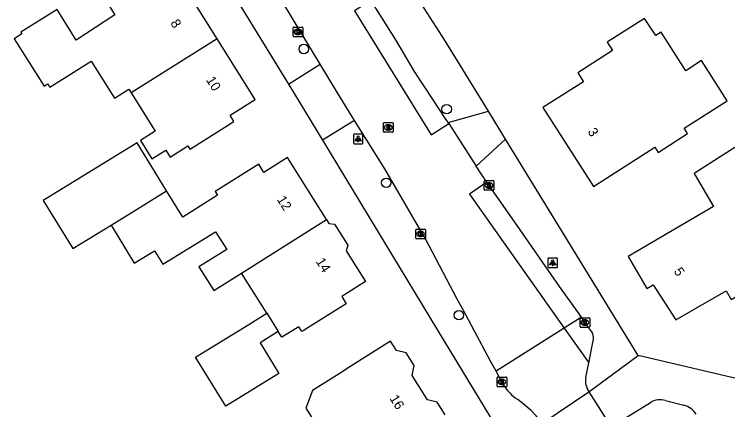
# Model space of a CAD drawing. Extents: x 161354 to 161876, y 382161 to 382804.
# Drawn here: x 161455.3 to 161529.3, y 382580.4 to 382621.3 of the extents above; entities that cross this region are included whole.
import ezdxf

# ---------------------------------------------------------------- set-up
doc = ezdxf.new("R2010")
doc.units = 0
for name, color, linetype in [('IMGEO_Boom', 7, 'Continuous'), ('IMGEO_Kolk', 7, 'Continuous'), ('IMGEO_Lichtpunt', 7, 'Continuous'), ('IMGEO_Pand', 7, 'Continuous'), ('IMGEO_Pand_nummerreeks', 7, 'Continuous'), ('IMGEO_Parkeervlak_gesloten', 7, 'Continuous'), ('IMGEO_Rijbaan_lokaal_gesloten', 7, 'Continuous'), ('IMGEO_Rijbaan_lokaal_open', 7, 'Continuous'), ('IMGEO_Rioolput', 7, 'Continuous'), ('IMGEO_Voetpad_open', 7, 'Continuous')]:
    doc.layers.add(name, color=color, linetype=linetype)

msp = doc.modelspace()

# ---------------------------------------------------------------- linework, layer by layer
at = {"layer": 'IMGEO_Boom'}
for centre in [(161485.332, 382617.715), (161500.14, 382611.487), (161493.875, 382603.871), (161501.41, 382590.158)]:
    msp.add_circle(centre, 0.489, dxfattribs=at)
at = {"layer": 'IMGEO_Kolk'}
for p, q in [((161484.232, 382619.064), (161484.232, 382619.916)), ((161484.307, 382619.99), (161485.159, 382619.99)), ((161485.233, 382619.916), (161485.233, 382619.064)), ((161484.743, 382619.21), (161484.718, 382619.21)), ((161484.72, 382619.77), (161484.745, 382619.77)), ((161485.159, 382618.99), (161484.307, 382618.99)), ((161504.036, 382603.163), (161504.036, 382604.015)), ((161504.111, 382604.089), (161504.963, 382604.089)), ((161504.524, 382603.869), (161504.549, 382603.869)), ((161505.037, 382604.015), (161505.037, 382603.163)), ((161504.963, 382603.089), (161504.111, 382603.089)), ((161504.547, 382603.309), (161504.522, 382603.309)), ((161496.933, 382598.142), (161496.933, 382598.994)), ((161497.008, 382599.068), (161497.86, 382599.068)), ((161497.421, 382598.848), (161497.446, 382598.848)), ((161497.934, 382598.994), (161497.934, 382598.142)), ((161497.86, 382598.068), (161497.008, 382598.068)), ((161497.444, 382598.288), (161497.419, 382598.288)), ((161513.962, 382588.975), (161513.962, 382589.827)), ((161514.037, 382589.901), (161514.889, 382589.901)), ((161514.45, 382589.681), (161514.475, 382589.681)), ((161514.963, 382589.827), (161514.963, 382588.975)), ((161514.889, 382588.901), (161514.037, 382588.901)), ((161514.473, 382589.121), (161514.448, 382589.121)), ((161505.436, 382583.748), (161506.288, 382583.748)), ((161505.361, 382582.822), (161505.361, 382583.674)), ((161505.872, 382582.968), (161505.847, 382582.968)), ((161505.849, 382583.528), (161505.874, 382583.528)), ((161506.362, 382583.674), (161506.362, 382582.822)), ((161506.288, 382582.748), (161505.436, 382582.748))]:
    msp.add_line(p, q, dxfattribs=at)
for points in [[(161484.232, 382619.064), (161484.232, 382619.916)], [(161484.307, 382619.99), (161485.159, 382619.99)], [(161485.233, 382619.916), (161485.233, 382619.064)], [(161484.553, 382619.69), (161484.676, 382619.69), (161484.676, 382619.539), (161484.806, 382619.69), (161484.97, 382619.69), (161484.824, 382619.539), (161484.977, 382619.29), (161484.825, 382619.29), (161484.74, 382619.454), (161484.676, 382619.387), (161484.676, 382619.29), (161484.553, 382619.29), (161484.553, 382619.69)], [(161485.159, 382618.99), (161484.307, 382618.99)], [(161504.036, 382603.163), (161504.036, 382604.015)], [(161504.111, 382604.089), (161504.963, 382604.089)], [(161504.357, 382603.789), (161504.48, 382603.789), (161504.48, 382603.638), (161504.61, 382603.789), (161504.774, 382603.789), (161504.628, 382603.638), (161504.781, 382603.389), (161504.629, 382603.389), (161504.544, 382603.553), (161504.48, 382603.486), (161504.48, 382603.389), (161504.357, 382603.389), (161504.357, 382603.789)], [(161505.037, 382604.015), (161505.037, 382603.163)], [(161504.963, 382603.089), (161504.111, 382603.089)], [(161496.933, 382598.142), (161496.933, 382598.994)], [(161497.008, 382599.068), (161497.86, 382599.068)], [(161497.254, 382598.768), (161497.377, 382598.768), (161497.377, 382598.617), (161497.507, 382598.768), (161497.671, 382598.768), (161497.525, 382598.617), (161497.678, 382598.368), (161497.526, 382598.368), (161497.441, 382598.532), (161497.377, 382598.465), (161497.377, 382598.368), (161497.254, 382598.368), (161497.254, 382598.768)], [(161497.934, 382598.994), (161497.934, 382598.142)], [(161497.86, 382598.068), (161497.008, 382598.068)], [(161513.962, 382588.975), (161513.962, 382589.827)], [(161514.037, 382589.901), (161514.889, 382589.901)], [(161514.283, 382589.601), (161514.406, 382589.601), (161514.406, 382589.45), (161514.536, 382589.601), (161514.7, 382589.601), (161514.554, 382589.45), (161514.707, 382589.201), (161514.555, 382589.201), (161514.47, 382589.365), (161514.406, 382589.298), (161514.406, 382589.201), (161514.283, 382589.201), (161514.283, 382589.601)], [(161514.963, 382589.827), (161514.963, 382588.975)], [(161514.889, 382588.901), (161514.037, 382588.901)], [(161505.436, 382583.748), (161506.288, 382583.748)], [(161505.361, 382582.822), (161505.361, 382583.674)], [(161505.682, 382583.448), (161505.805, 382583.448), (161505.805, 382583.297), (161505.935, 382583.448), (161506.099, 382583.448), (161505.953, 382583.297), (161506.106, 382583.048), (161505.954, 382583.048), (161505.869, 382583.212), (161505.805, 382583.145), (161505.805, 382583.048), (161505.682, 382583.048), (161505.682, 382583.448)], [(161506.362, 382583.674), (161506.362, 382582.822)], [(161506.288, 382582.748), (161505.436, 382582.748)]]:
    msp.add_lwpolyline(points, dxfattribs=at)
for centre, start, end in [((161484.309, 382619.914), 91.55205, 178.44795), ((161484.309, 382619.914), 91.55205, 178.44795), ((161485.157, 382619.914), 1.55205, 88.44795), ((161485.157, 382619.914), 1.55205, 88.44795), ((161484.309, 382619.066), 181.55205, 268.44795), ((161484.309, 382619.066), 181.55205, 268.44795), ((161485.157, 382619.066), 271.55205, 358.44795), ((161485.157, 382619.066), 271.55205, 358.44795), ((161504.113, 382604.013), 91.55205, 178.44795), ((161504.113, 382604.013), 91.55205, 178.44795), ((161504.961, 382604.013), 1.55205, 88.44795), ((161504.961, 382604.013), 1.55205, 88.44795), ((161504.113, 382603.165), 181.55205, 268.44795), ((161504.113, 382603.165), 181.55205, 268.44795), ((161504.961, 382603.165), 271.55205, 358.44795), ((161504.961, 382603.165), 271.55205, 358.44795), ((161497.01, 382598.992), 91.55205, 178.44795), ((161497.01, 382598.992), 91.55205, 178.44795), ((161497.858, 382598.992), 1.55205, 88.44795), ((161497.858, 382598.992), 1.55205, 88.44795), ((161497.01, 382598.144), 181.55205, 268.44795), ((161497.01, 382598.144), 181.55205, 268.44795), ((161497.858, 382598.144), 271.55205, 358.44795), ((161497.858, 382598.144), 271.55205, 358.44795), ((161514.039, 382589.825), 91.55205, 178.44795), ((161514.039, 382589.825), 91.55205, 178.44795), ((161514.887, 382589.825), 1.55205, 88.44795), ((161514.887, 382589.825), 1.55205, 88.44795), ((161514.039, 382588.977), 181.55205, 268.44795), ((161514.039, 382588.977), 181.55205, 268.44795), ((161514.887, 382588.977), 271.55205, 358.44795), ((161514.887, 382588.977), 271.55205, 358.44795), ((161505.438, 382583.672), 91.55205, 178.44795), ((161505.438, 382583.672), 91.55205, 178.44795), ((161506.286, 382583.672), 1.55205, 88.44795), ((161506.286, 382583.672), 1.55205, 88.44795), ((161505.438, 382582.824), 181.55205, 268.44795), ((161505.438, 382582.824), 181.55205, 268.44795), ((161506.286, 382582.824), 271.55205, 358.44795), ((161506.286, 382582.824), 271.55205, 358.44795)]:
    msp.add_arc(centre, 0.0765, start, end, dxfattribs=at)
for centre, major_axis, ratio, start_param, end_param in [((161484.719, 382619.49), (-0.387, 0.002), 0.722429, 4.712389, 7.853982), ((161484.744, 382619.49), (-0.39, 0.002), 0.717154, 1.570796, 4.712389), ((161504.523, 382603.589), (-0.387, 0.002), 0.722429, 4.712389, 7.853982), ((161504.548, 382603.589), (-0.39, 0.002), 0.717154, 1.570796, 4.712389), ((161497.42, 382598.568), (-0.387, 0.002), 0.722429, 4.712389, 7.853982), ((161497.445, 382598.568), (-0.39, 0.002), 0.717154, 1.570796, 4.712389), ((161514.449, 382589.401), (-0.387, 0.002), 0.722429, 4.712389, 7.853982), ((161514.474, 382589.401), (-0.39, 0.002), 0.717154, 1.570796, 4.712389), ((161505.848, 382583.248), (-0.387, 0.002), 0.722429, 4.712389, 7.853982), ((161505.873, 382583.248), (-0.39, 0.002), 0.717154, 1.570796, 4.712389)]:
    msp.add_ellipse(centre, major_axis=major_axis, ratio=ratio, start_param=start_param, end_param=end_param, dxfattribs=at)
at = {"layer": 'IMGEO_Lichtpunt'}
for p, q in [((161490.471, 382608.814), (161490.471, 382608.007)), ((161490.471, 382608.814), (161490.471, 382608.007)), ((161491.373, 382608.909), (161490.565, 382608.909)), ((161491.373, 382608.909), (161490.565, 382608.909)), ((161491.467, 382608.007), (161491.467, 382608.814)), ((161491.467, 382608.007), (161491.467, 382608.814)), ((161490.565, 382607.913), (161491.373, 382607.913)), ((161490.565, 382607.913), (161491.373, 382607.913)), ((161510.624, 382595.981), (161510.624, 382595.174)), ((161510.624, 382595.981), (161510.624, 382595.174)), ((161511.526, 382596.076), (161510.718, 382596.076)), ((161511.526, 382596.076), (161510.718, 382596.076)), ((161511.62, 382595.174), (161511.62, 382595.981)), ((161511.62, 382595.174), (161511.62, 382595.981)), ((161510.718, 382595.08), (161511.526, 382595.08)), ((161510.718, 382595.08), (161511.526, 382595.08))]:
    msp.add_line(p, q, dxfattribs=at)
for points in [[(161490.845, 382608.478), (161490.884, 382608.45), (161490.696, 382608.188), (161490.658, 382608.215), (161490.845, 382608.478)], [(161490.947, 382608.43), (161490.994, 382608.43), (161490.994, 382608.108), (161490.947, 382608.108), (161490.947, 382608.43)], [(161491.057, 382608.45), (161491.095, 382608.477), (161491.282, 382608.215), (161491.243, 382608.187), (161491.057, 382608.45)], [(161510.998, 382595.645), (161511.037, 382595.617), (161510.849, 382595.355), (161510.811, 382595.382), (161510.998, 382595.645)], [(161511.1, 382595.597), (161511.147, 382595.597), (161511.147, 382595.275), (161511.1, 382595.275), (161511.1, 382595.597)], [(161511.21, 382595.617), (161511.248, 382595.644), (161511.435, 382595.382), (161511.396, 382595.354), (161511.21, 382595.617)]]:
    msp.add_lwpolyline(points, dxfattribs=at)
for centre in [(161490.97, 382608.612), (161511.123, 382595.779)]:
    msp.add_circle(centre, 0.0994, dxfattribs=at)
for centre, start, end in [((161490.565, 382608.814), 90, 180), ((161490.565, 382608.814), 90, 180), ((161491.373, 382608.814), 0, 90), ((161491.373, 382608.814), 0, 90), ((161490.565, 382608.007), 180, 270), ((161490.565, 382608.007), 180, 270), ((161491.373, 382608.007), 270, 0), ((161491.373, 382608.007), 270, 360), ((161510.718, 382595.981), 90, 180), ((161510.718, 382595.981), 90, 180), ((161511.526, 382595.981), 0, 90), ((161511.526, 382595.981), 0, 90), ((161510.718, 382595.174), 180, 270), ((161510.718, 382595.174), 180, 270), ((161511.526, 382595.174), 270, 0), ((161511.526, 382595.174), 270, 360)]:
    msp.add_arc(centre, 0.0946, start, end, dxfattribs=at)
at = {"layer": 'IMGEO_Pand'}
for points in [[(161476.368, 382618.775), (161472.42, 382625.057), (161469.853, 382623.444), (161469.094, 382624.652), (161465.175, 382622.189), (161465.761, 382621.258), (161461.76, 382618.626), (161459.765, 382621.802), (161456.015, 382619.445), (161456.122, 382619.276), (161455.335, 382618.782), (161458.416, 382613.881), (161458.792, 382614.118), (161459.015, 382613.762), (161463.307, 382616.459), (161465.723, 382612.615), (161467.215, 382613.553), (161467.454, 382613.173)], [(161520.354, 382606.692), (161521.716, 382607.564), (161522.071, 382607.009), (161525.112, 382608.956), (161524.756, 382609.51), (161529.198, 382612.354), (161526.536, 382616.513), (161524.908, 382615.471), (161522.358, 382619.455), (161521.829, 382619.116), (161520.641, 382620.888), (161516.784, 382618.417), (161517.328, 382617.566), (161513.723, 382615.258), (161514.315, 382614.332), (161510.12, 382611.646), (161515.345, 382603.485), (161520.354, 382606.692)], [(161467.454, 382613.173), (161469.94, 382609.218), (161468.409, 382608.256), (161469.604, 382606.355), (161471.042, 382607.259), (161471.497, 382606.535), (161473.322, 382607.682), (161473.527, 382607.355), (161473.862, 382607.566), (161478.095, 382610.226), (161477.7, 382610.854), (161480.313, 382612.497), (161476.368, 382618.775)], [(161476.368, 382618.775), (161467.454, 382613.173)], [(161523.9, 382589.662), (161529.1, 382592.687), (161529.627, 382591.781), (161533.997, 382594.323), (161533.666, 382594.894), (161535.542, 382595.986), (161532.083, 382601.934), (161535.61, 382603.986), (161532.589, 382609.182), (161525.776, 382604.825), (161527.773, 382601.394), (161518.94, 382596.251), (161520.875, 382592.926), (161521.528, 382593.306), (161523.9, 382589.662)], [(161471.125, 382603.016), (161468.076, 382607.993), (161458.345, 382602.032), (161461.393, 382597.056), (161465.363, 382599.487)], [(161487.695, 382600.06), (161483.661, 382606.478), (161481.2, 382604.932), (161480.66, 382605.791), (161476.162, 382602.965), (161476.407, 382602.575), (161472.788, 382600.3), (161471.125, 382603.016)], [(161465.363, 382599.487), (161467.456, 382600.769), (161471.125, 382603.016)], [(161478.886, 382594.523), (161487.695, 382600.06)], [(161487.695, 382600.06), (161487.944, 382599.663), (161488.529, 382599.581), (161489.894, 382597.41), (161489.735, 382596.815), (161491.73, 382593.639), (161489.261, 382592.087), (161489.728, 382591.345), (161485.495, 382588.684), (161485.326, 382588.578), (161485.131, 382588.456), (161484.809, 382588.968), (161483.066, 382587.873), (161482.684, 382588.481)], [(161465.363, 382599.487), (161467.775, 382595.551), (161469.868, 382596.833), (161470.723, 382595.437), (161473.306, 382597.019), (161476.202, 382598.793), (161477.349, 382596.968), (161474.474, 382595.161), (161476.011, 382592.716), (161478.886, 382594.523)], [(161481.5, 382590.364), (161478.886, 382594.523)], [(161482.684, 382588.481), (161480.801, 382587.299), (161482.758, 382584.127), (161477.247, 382580.726), (161474.113, 382585.805), (161479.624, 382589.206), (161481.5, 382590.364)], [(161481.5, 382590.364), (161482.684, 382588.481)], [(161499.981, 382579.838), (161499.145, 382581.167), (161498.139, 382581.41), (161496.563, 382583.918), (161496.768, 382584.946), (161495.948, 382586.249), (161494.932, 382586.508), (161494.337, 382587.456), (161490.104, 382584.796), (161489.002, 382584.103), (161486.221, 382582.354), (161485.548, 382580.525), (161486.433, 382579.117)]]:
    msp.add_lwpolyline(points, dxfattribs=at)
at = {"layer": 'IMGEO_Parkeervlak_gesloten'}
msp.add_lwpolyline([(161514.103, 382589.941), (161512.323, 382588.818)], dxfattribs=at)
at = {"layer": 'IMGEO_Rijbaan_lokaal_gesloten'}
for points in [[(161487.021, 382616.156), (161481.316, 382625.612), (161479.131, 382629.072)], [(161492.318, 382622.744), (161490.582, 382621.666), (161498.546, 382608.84), (161500.362, 382610.003)], [(161490.603, 382610.323), (161488.824, 382613.19), (161487.021, 382616.156)], [(161505.262, 382584.363), (161504.697, 382585.412), (161501.836, 382590.717), (161501.232, 382591.815), (161497.961, 382598.054), (161493.723, 382605.297), (161490.603, 382610.323)], [(161500.362, 382610.003), (161503.184, 382605.598)], [(161504.307, 382603.915), (161503.775, 382604.675), (161503.184, 382605.598)], [(161504.307, 382603.915), (161502.521, 382602.689), (161512.323, 382588.818)], [(161512.323, 382588.818), (161505.262, 382584.363)]]:
    msp.add_lwpolyline(points, dxfattribs=at)
at = {"layer": 'IMGEO_Rijbaan_lokaal_open'}
for points in [[(161512.323, 382588.818), (161514.859, 382585.229)], [(161514.562, 382583.739), (161514.859, 382585.229)], [(161506.009, 382582.961), (161505.862, 382583.248), (161505.262, 382584.363)], [(161510.003, 382578.937), (161514.869, 382582.227)], [(161514.869, 382582.227), (161517.208, 382578.534)], [(161510.003, 382578.937), (161509.898, 382579.107), (161509.418, 382579.731), (161508.881, 382580.305), (161508.29, 382580.825), (161507.501, 382581.426)]]:
    msp.add_lwpolyline(points, dxfattribs=at)
for centre, radius, start, end in [((161516.602, 382583.366), 2.074, 169.64267, 213.31221), ((161510.428, 382585.763), 5.233, 212.38305, 235.98923)]:
    msp.add_arc(centre, radius, start, end, dxfattribs=at)
at = {"layer": 'IMGEO_Rioolput'}
for p, q in [((161493.593, 382609.175), (161493.593, 382610.027)), ((161493.668, 382610.101), (161494.52, 382610.101)), ((161494.081, 382609.881), (161494.106, 382609.881)), ((161494.594, 382610.027), (161494.594, 382609.175)), ((161494.52, 382609.101), (161493.668, 382609.101)), ((161494.104, 382609.321), (161494.079, 382609.321))]:
    msp.add_line(p, q, dxfattribs=at)
for points in [[(161493.593, 382609.175), (161493.593, 382610.027)], [(161493.668, 382610.101), (161494.52, 382610.101)], [(161494.182, 382609.799), (161493.93, 382609.801), (161493.93, 382609.401)], [(161493.93, 382609.401), (161494.054, 382609.401), (161494.054, 382609.563), (161494.065, 382609.563)], [(161494.108, 382609.72), (161494.054, 382609.72), (161494.054, 382609.639)], [(161494.054, 382609.639), (161494.106, 382609.639)], [(161494.594, 382610.027), (161494.594, 382609.175)], [(161494.52, 382609.101), (161493.668, 382609.101)], [(161494.112, 382609.534), (161494.183, 382609.401), (161494.323, 382609.401), (161494.258, 382609.527)]]:
    msp.add_lwpolyline(points, dxfattribs=at)
for centre, radius, start, end in [((161493.67, 382610.025), 0.0765, 91.55205, 178.44795), ((161493.67, 382610.025), 0.0765, 91.55205, 178.44795), ((161494.064, 382609.51), 0.0533, 26.02933, 88.69889), ((161494.09, 382609.828), 0.19, 274.7715, 282.96867), ((161494.114, 382609.624), 0.0964, 77.00612, 93.18647), ((161494.128, 382609.681), 0.0378, 276.66336, 79.67722), ((161494.181, 382609.689), 0.109, 350.36119, 89.41601), ((161494.179, 382609.689), 0.112, 277.58423, 350.98172), ((161494.163, 382609.474), 0.108, 29.51342, 73.79051), ((161494.518, 382610.025), 0.0765, 1.55205, 88.44795), ((161494.518, 382610.025), 0.0765, 1.55205, 88.44795), ((161493.67, 382609.177), 0.0765, 181.55205, 268.44795), ((161493.67, 382609.177), 0.0765, 181.55205, 268.44795), ((161494.518, 382609.177), 0.0765, 271.55205, 358.44795), ((161494.518, 382609.177), 0.0765, 271.55205, 358.44795)]:
    msp.add_arc(centre, radius, start, end, dxfattribs=at)
for centre, major_axis, ratio, start_param, end_param in [((161494.08, 382609.601), (-0.387, 0.002), 0.722429, 4.712389, 7.853982), ((161494.105, 382609.601), (-0.39, 0.002), 0.717154, 1.570796, 4.712389)]:
    msp.add_ellipse(centre, major_axis=major_axis, ratio=ratio, start_param=start_param, end_param=end_param, dxfattribs=at)
at = {"layer": 'IMGEO_Voetpad_open'}
for points in [[(161628.452, 382648.518), (161612.356, 382637.679), (161612.276, 382637.879), (161577.471, 382614.736), (161574.373, 382612.676), (161556.508, 382600.797), (161530.719, 382583.477), (161519.986, 382585.99)], [(161475.768, 382627.098), (161483.738, 382614.059)], [(161504.473, 382611.274), (161500, 382618.564), (161494.69, 382626.794)], [(161500.298, 382610.103), (161500.165, 382610.311), (161500, 382610.56), (161498.744, 382612.459), (161496.814, 382615.387), (161494.873, 382618.666), (161492.642, 382622.223), (161492.318, 382622.744)], [(161483.738, 382614.059), (161487.021, 382616.156)], [(161483.738, 382614.059), (161487.262, 382608.293)], [(161500.298, 382610.103), (161504.473, 382611.274)], [(161506.241, 382608.392), (161504.473, 382611.274)], [(161490.603, 382610.323), (161487.262, 382608.293)], [(161500.362, 382610.003), (161500.298, 382610.103)], [(161487.262, 382608.293), (161500, 382587.3), (161505.762, 382577.804)], [(161503.184, 382605.598), (161506.241, 382608.392)], [(161519.986, 382585.99), (161506.241, 382608.392)], [(161514.103, 382589.941), (161513.711, 382590.528), (161511.817, 382593.143), (161507.756, 382598.989), (161504.307, 382603.915)], [(161515.171, 382588.443), (161514.463, 382589.401), (161514.103, 382589.941)], [(161514.859, 382585.229), (161515.344, 382587.665)], [(161514.869, 382582.227), (161519.986, 382585.99)], [(161517.846, 382578.27), (161518.135, 382578.476), (161517.841, 382578.999), (161521.263, 382581.103)], [(161522.81, 382581.312), (161524.721, 382580.835)]]:
    msp.add_lwpolyline(points, dxfattribs=at)
for centre, radius, start, end in [((161514.332, 382587.848), 1.028, 349.73097, 35.34224), ((161522.238, 382579.712), 1.699, 70.33771, 125.05047), ((161524.296, 382578.952), 1.93, 29.44103, 77.28773)]:
    msp.add_arc(centre, radius, start, end, dxfattribs=at)

# ---------------------------------------------------------------- texts
at = {"layer": 'IMGEO_Pand_nummerreeks'}
for s, rotation, p in [('8', 302.14845, (161471.472, 382620.402)), ('10', 302.14622, (161475.172, 382614.512)), ('3', 302.62974, (161514.706, 382609.155)), ('12', 302.14845, (161482.508, 382602.147)), ('14', 302.14845, (161486.544, 382595.725)), ('5', 303.06143, (161523.626, 382594.703)), ('16', 302.14272, (161494.183, 382581.541))]:
    msp.add_text(s, height=1, rotation=rotation, dxfattribs=at).set_placement(p)

doc.saveas('drawing.dxf')
